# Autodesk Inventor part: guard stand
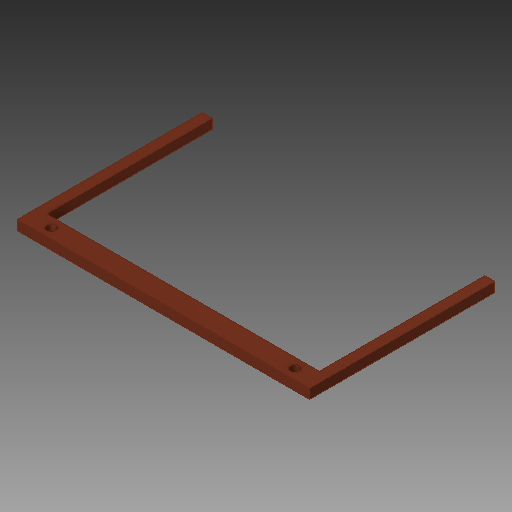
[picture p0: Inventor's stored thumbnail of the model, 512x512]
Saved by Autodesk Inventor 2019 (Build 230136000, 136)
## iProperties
Created: 2021-07
Part Number: guard stand
Material: Copper, Alloy
Document SubType Name: Modeling
Designer: Avinash
Density: 8.92 g/cm^3
Appearance: Copper - Satin
Author: Avinash
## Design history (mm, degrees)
sketch "Sketch5"
  geometry: L1 (0, 0)-(-300, 0); L2 (-300, 0)-(-300, 10); L3 (-300, 10)-(0, 10); L4 (0, 10)-(0, 0)
  constraints: 8 end point, 2 parallel, 1 horizontal, 1 perpendicular
  dimensions: "d22" = 10 distance of L1.end L2.end; "d23" = 300 distance of L2.end L3.end
extrude "Extrusion5" new body sketch "Sketch5" distance "d24" = 20; taper "d25" = 0 deg
sketch "Sketch6"
  geometry: L1 (0, 0)-(0, 10) reference; L2 (300, 0)-(0, 0) reference; L3 (0, 10)-(10, 10); L4 (10, 10)-(10, 0); L5 (10, 0)-(0, 0); L6 (0, 0)-(0, 10); L7 (0, 10)-(300, 10) reference; L8 (300, 10)-(290, 10); L9 (290, 10)-(290, 0); L10 (290, 0)-(300, 0); L11 (300, 0)-(300, 10)
  constraints: 16 end point, 4 parallel, 2 horizontal, 2 perpendicular, 2 point on line
  dimensions: "d26" = 10 distance of L4.end L5.end; "d27" = 10 distance of L10.end L9.end
extrude "Extrusion6" join sketch "Sketch6" distance "d28" = 170; taper "d29" = 0 deg
sketch "Sketch7"
  geometry: L1 (300, -190)-(300, 0) reference; L2 (290, -20)-(10, -20) reference; L3 (0, 0)-(0, -190) reference; C1 r 5 at (275, -10); C2 r 5 at (25, -10); 1 further point
  constraints: 2 centre point
  dimensions: "d30" = 10 diameter of C1; "d31" = 10 diameter of C2; "d32" = 25 distance from line of L1 C1.centre; "d33" = 10 distance from line of L2 C1.centre; "d34" = 10 distance from line of L2 C2.centre; "d35" = 25 distance from line of L3 C2.centre
extrude "Extrusion7" cut sketch "Sketch7" distance "d36" = 50; taper "d37" = 0 deg
body "Solid2"
